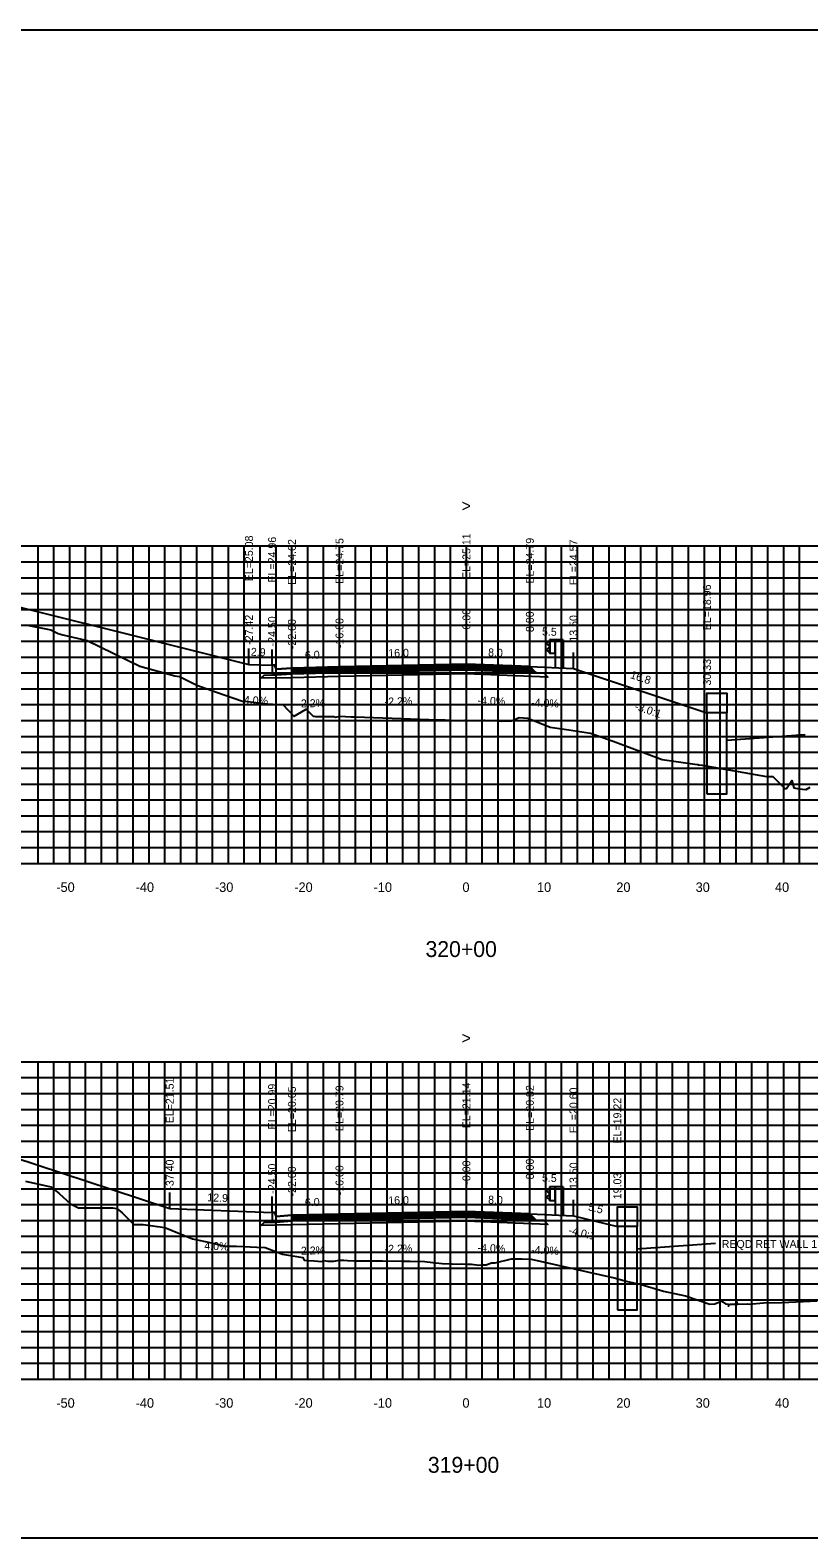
# Model space of a CAD drawing. Extents: x 1797652 to 1804145, y 245981 to 250269.
# Drawn here: x 1802916 to 1803014.2, y 250079.4 to 250269.4 of the extents above; entities that cross this region are included whole.
import ezdxf

# ---------------------------------------------------------------- set-up
doc = ezdxf.new("R2010")
doc.units = 0
for name, color, linetype in [('1', 7, 'Continuous'), ('10', 7, 'Continuous'), ('3', 7, 'Continuous'), ('4', 7, 'Continuous'), ('60', 7, 'Continuous'), ('BASE', 7, 'Continuous'), ('CL-CNST', 7, 'Continuous'), ('Level 1', 7, 'Continuous'), ('Level 62', 7, 'Continuous'), ('LOWER BINDER', 7, 'Continuous'), ('M-ROADS', 7, 'Continuous'), ('UPPER BINDER', 7, 'Continuous'), ('WEARING', 7, 'Continuous')]:
    doc.layers.add(name, color=color, linetype=linetype)

msp = doc.modelspace()

# ---------------------------------------------------------------- linework, layer by layer
for p, q in [((1802943.59, 250189.51), (1802943.59, 250191.51)), ((1802946.5, 250189.39), (1802946.5, 250191.39)), ((1802949, 250189.05), (1802949, 250191.05)), ((1802955, 250189.19), (1802955, 250191.19)), ((1802971, 250189.54), (1802971, 250191.54)), ((1802979, 250189.22), (1802979, 250191.22)), ((1802984.5, 250189), (1802984.5, 250191)), ((1803001.33, 250183.39), (1803001.33, 250185.39)), ((1802933.6, 250120.94), (1802933.6, 250122.94)), ((1802946.5, 250120.43), (1802946.5, 250122.43)), ((1802949, 250120.09), (1802949, 250122.09)), ((1802955, 250120.22), (1802955, 250122.22)), ((1802971, 250120.57), (1802971, 250122.57)), ((1802979, 250120.25), (1802979, 250122.25)), ((1802984.5, 250120.03), (1802984.5, 250122.03)), ((1802990.03, 250118.65), (1802990.03, 250120.65))]:
    msp.add_line(p, q)
for points in [[(1802821, 250079.43), (1803121, 250079.43), (1803121, 250269.43), (1802821, 250269.43)], [(1802949, 250189.05), (1802947, 250188.89), (1802946.83, 250189.39), (1802946.5, 250189.39), (1802946.5, 250188.17), (1802947, 250188.17), (1802949, 250188.33)], [(1802949, 250120.09), (1802947, 250119.93), (1802946.83, 250120.43), (1802946.5, 250120.43), (1802946.5, 250119.21), (1802947, 250119.21), (1802949, 250119.37)]]:
    msp.add_lwpolyline(points, close=True)
at = {"layer": '3'}
for p, q in [((1803013.72, 250180.62), (1803003.83, 250179.91)), ((1803002.42, 250116.53), (1802992.53, 250115.82))]:
    msp.add_line(p, q, dxfattribs=at)
at = {"layer": '60'}
for p, q in [((1802821, 250164.43), (1803121, 250164.43)), ((1802921, 250164.37), (1802921, 250164.43)), ((1802931, 250164.37), (1802931, 250164.43)), ((1802941, 250164.37), (1802941, 250164.43)), ((1802951, 250164.37), (1802951, 250164.43)), ((1802961, 250164.37), (1802961, 250164.43)), ((1802971, 250164.37), (1802971, 250164.43)), ((1802981, 250164.37), (1802981, 250164.43)), ((1802991, 250164.37), (1802991, 250164.43)), ((1803001, 250164.37), (1803001, 250164.43)), ((1803011, 250164.37), (1803011, 250164.43)), ((1802821, 250099.43), (1803121, 250099.43)), ((1802921, 250099.37), (1802921, 250099.43)), ((1802931, 250099.37), (1802931, 250099.43)), ((1802941, 250099.37), (1802941, 250099.43)), ((1802951, 250099.37), (1802951, 250099.43)), ((1802961, 250099.37), (1802961, 250099.43)), ((1802971, 250099.37), (1802971, 250099.43)), ((1802981, 250099.37), (1802981, 250099.43)), ((1802991, 250099.37), (1802991, 250099.43)), ((1803001, 250099.37), (1803001, 250099.43)), ((1803011, 250099.37), (1803011, 250099.43))]:
    msp.add_line(p, q, dxfattribs=at)
at = {"layer": 'BASE'}
for points in [[(1802949, 250188.33), (1802955, 250188.47), (1802971, 250188.82), (1802979.75, 250188.47), (1802980.75, 250188.43), (1802981.27, 250187.91), (1802971, 250188.32), (1802955, 250187.97), (1802949, 250187.83), (1802945.09, 250187.75), (1802945.5, 250188.15), (1802946.5, 250188.17), (1802947, 250188.17)], [(1802949, 250119.37), (1802955, 250119.5), (1802971, 250119.85), (1802979.75, 250119.5), (1802980.75, 250119.46), (1802981.27, 250118.94), (1802971, 250119.35), (1802955, 250119), (1802949, 250118.87), (1802945.09, 250118.78), (1802945.5, 250119.18), (1802946.5, 250119.21), (1802947, 250119.21)]]:
    msp.add_lwpolyline(points, close=True, dxfattribs=at)
at = {"layer": 'CL-CNST'}
for points in [[(1802908.08, 250198.35), (1802928.03, 250193.38), (1802943.59, 250189.51)], [(1802943.59, 250189.51), (1802946.5, 250189.39), (1802946.83, 250189.39), (1802947, 250188.89), (1802949, 250189.05), (1802955, 250189.19), (1802971, 250189.54), (1802979, 250189.22), (1802984.5, 250189), (1803001.33, 250183.39)], [(1802821, 250132.88), (1802827, 250133.14), (1802834.09, 250133.44), (1802839.28, 250133.66), (1802849.92, 250134.11), (1802851.54, 250134.17), (1802853.51, 250134.26), (1802863.8, 250134.69), (1802872.2, 250135.05), (1802876.07, 250135.21), (1802876.73, 250135.18), (1802877.09, 250135.17), (1802877.12, 250135.13), (1802877.14, 250135.11), (1802880.65, 250135.02), (1802886.29, 250134.87), (1802887.43, 250134.83), (1802888.33, 250134.79), (1802889.97, 250134.72), (1802891.91, 250134.64), (1802926.35, 250123.32), (1802933.6, 250120.94)], [(1802933.6, 250120.94), (1802946.5, 250120.43), (1802946.83, 250120.43), (1802947, 250119.93), (1802949, 250120.09), (1802955, 250120.22), (1802971, 250120.57), (1802979, 250120.25), (1802984.5, 250120.03), (1802990.03, 250118.65)]]:
    msp.add_lwpolyline(points, dxfattribs=at)
for points in [[(1803003.83, 250183.39), (1803001.33, 250183.39), (1803001.33, 250185.89), (1803003.83, 250185.89)], [(1803001.33, 250173.18), (1803003.83, 250173.18), (1803003.83, 250183.39), (1803001.33, 250183.39)], [(1802992.53, 250118.65), (1802990.03, 250118.65), (1802990.03, 250121.15), (1802992.53, 250121.15)], [(1802990.03, 250108.18), (1802992.53, 250108.18), (1802992.53, 250118.65), (1802990.03, 250118.65)]]:
    msp.add_lwpolyline(points, close=True, dxfattribs=at)
at = {"layer": 'Level 1'}
for p, q in [((1802981.46, 250192.47), (1802981.1, 250192.17)), ((1802981.1, 250192.1), (1802981.46, 250191.81)), ((1802981.46, 250192.62), (1802981.46, 250190.87)), ((1802983.21, 250192.62), (1802981.46, 250192.62)), ((1802981.51, 250192.62), (1802981.51, 250190.87)), ((1802982.16, 250192.62), (1802982.16, 250190.87)), ((1802982.21, 250192.62), (1802982.21, 250189.09)), ((1802983.21, 250192.62), (1802983.21, 250189.05)), ((1802981.46, 250191.67), (1802981.1, 250191.37)), ((1802981.1, 250191.3), (1802981.46, 250191.02)), ((1802982.21, 250190.87), (1802981.46, 250190.87)), ((1802981.46, 250123.65), (1802981.46, 250121.9)), ((1802983.21, 250123.65), (1802981.46, 250123.65)), ((1802981.51, 250123.65), (1802981.51, 250121.9)), ((1802982.16, 250123.65), (1802982.16, 250121.9)), ((1802982.21, 250123.65), (1802982.21, 250120.12)), ((1802983.21, 250123.65), (1802983.21, 250120.08)), ((1802981.46, 250123.5), (1802981.1, 250123.2)), ((1802981.1, 250123.13), (1802981.46, 250122.84)), ((1802981.46, 250122.7), (1802981.1, 250122.4)), ((1802981.1, 250122.33), (1802981.46, 250122.05)), ((1802982.21, 250121.9), (1802981.46, 250121.9))]:
    msp.add_line(p, q, dxfattribs=at)
for centre in [(1802981.13, 250192.13), (1802981.13, 250191.34), (1802981.13, 250123.16), (1802981.13, 250122.37)]:
    msp.add_arc(centre, 0.05, 135, 226.6208, dxfattribs=at)
at = {"layer": 'Level 62'}
for p, q in [((1802821, 250204.43), (1803121, 250204.43)), ((1802917, 250164.43), (1802917, 250204.43)), ((1802919, 250164.43), (1802919, 250204.43)), ((1802921, 250164.43), (1802921, 250204.43)), ((1802923, 250164.43), (1802923, 250204.43)), ((1802925, 250164.43), (1802925, 250204.43)), ((1802927, 250164.43), (1802927, 250204.43)), ((1802929, 250164.43), (1802929, 250204.43)), ((1802931, 250164.43), (1802931, 250204.43)), ((1802933, 250164.43), (1802933, 250204.43)), ((1802935, 250164.43), (1802935, 250204.43)), ((1802937, 250164.43), (1802937, 250204.43)), ((1802939, 250164.43), (1802939, 250204.43)), ((1802941, 250164.43), (1802941, 250204.43)), ((1802943, 250164.43), (1802943, 250204.43)), ((1802945, 250164.43), (1802945, 250204.43)), ((1802947, 250164.43), (1802947, 250204.43)), ((1802949, 250164.43), (1802949, 250204.43)), ((1802951, 250164.43), (1802951, 250204.43)), ((1802953, 250164.43), (1802953, 250204.43)), ((1802955, 250164.43), (1802955, 250204.43)), ((1802957, 250164.43), (1802957, 250204.43)), ((1802959, 250164.43), (1802959, 250204.43)), ((1802961, 250164.43), (1802961, 250204.43)), ((1802963, 250164.43), (1802963, 250204.43)), ((1802965, 250164.43), (1802965, 250204.43)), ((1802967, 250164.43), (1802967, 250204.43)), ((1802969, 250164.43), (1802969, 250204.43)), ((1802971, 250164.43), (1802971, 250204.43)), ((1802973, 250164.43), (1802973, 250204.43)), ((1802975, 250164.43), (1802975, 250204.43)), ((1802977, 250164.43), (1802977, 250204.43)), ((1802979, 250164.43), (1802979, 250204.43)), ((1802981, 250164.43), (1802981, 250204.43)), ((1802983, 250164.43), (1802983, 250204.43)), ((1802985, 250164.43), (1802985, 250204.43)), ((1802987, 250164.43), (1802987, 250204.43)), ((1802989, 250164.43), (1802989, 250204.43)), ((1802991, 250164.43), (1802991, 250204.43)), ((1802993, 250164.43), (1802993, 250204.43)), ((1802995, 250164.43), (1802995, 250204.43)), ((1802997, 250164.43), (1802997, 250204.43)), ((1802999, 250164.43), (1802999, 250204.43)), ((1803001, 250164.43), (1803001, 250204.43)), ((1803003, 250164.43), (1803003, 250204.43)), ((1803005, 250164.43), (1803005, 250204.43)), ((1803007, 250164.43), (1803007, 250204.43)), ((1803009, 250164.43), (1803009, 250204.43)), ((1803011, 250164.43), (1803011, 250204.43)), ((1803013, 250164.43), (1803013, 250204.43)), ((1802821, 250202.43), (1803121, 250202.43)), ((1802821, 250200.43), (1803121, 250200.43)), ((1802821, 250198.43), (1803121, 250198.43)), ((1802821, 250196.43), (1803121, 250196.43)), ((1802821, 250194.43), (1803121, 250194.43)), ((1802821, 250192.43), (1803121, 250192.43)), ((1802821, 250190.43), (1803121, 250190.43)), ((1802821, 250188.43), (1803121, 250188.43)), ((1802821, 250186.43), (1803121, 250186.43)), ((1802821, 250184.43), (1803121, 250184.43)), ((1802821, 250182.43), (1803121, 250182.43)), ((1802821, 250180.43), (1803121, 250180.43)), ((1802821, 250178.43), (1803121, 250178.43)), ((1802821, 250176.43), (1803121, 250176.43)), ((1802821, 250174.43), (1803121, 250174.43)), ((1802821, 250172.43), (1803121, 250172.43)), ((1802821, 250170.43), (1803121, 250170.43)), ((1802821, 250168.43), (1803121, 250168.43)), ((1802821, 250166.43), (1803121, 250166.43)), ((1802821, 250164.43), (1803121, 250164.43)), ((1802821, 250139.43), (1803121, 250139.43)), ((1802917, 250099.43), (1802917, 250139.43)), ((1802919, 250099.43), (1802919, 250139.43)), ((1802921, 250099.43), (1802921, 250139.43)), ((1802923, 250099.43), (1802923, 250139.43)), ((1802925, 250099.43), (1802925, 250139.43)), ((1802927, 250099.43), (1802927, 250139.43)), ((1802929, 250099.43), (1802929, 250139.43)), ((1802931, 250099.43), (1802931, 250139.43)), ((1802933, 250099.43), (1802933, 250139.43)), ((1802935, 250099.43), (1802935, 250139.43)), ((1802937, 250099.43), (1802937, 250139.43)), ((1802939, 250099.43), (1802939, 250139.43)), ((1802941, 250099.43), (1802941, 250139.43)), ((1802943, 250099.43), (1802943, 250139.43)), ((1802945, 250099.43), (1802945, 250139.43)), ((1802947, 250099.43), (1802947, 250139.43)), ((1802949, 250099.43), (1802949, 250139.43)), ((1802951, 250099.43), (1802951, 250139.43)), ((1802953, 250099.43), (1802953, 250139.43)), ((1802955, 250099.43), (1802955, 250139.43)), ((1802957, 250099.43), (1802957, 250139.43)), ((1802959, 250099.43), (1802959, 250139.43)), ((1802961, 250099.43), (1802961, 250139.43)), ((1802963, 250099.43), (1802963, 250139.43)), ((1802965, 250099.43), (1802965, 250139.43)), ((1802967, 250099.43), (1802967, 250139.43)), ((1802969, 250099.43), (1802969, 250139.43)), ((1802971, 250099.43), (1802971, 250139.43)), ((1802973, 250099.43), (1802973, 250139.43)), ((1802975, 250099.43), (1802975, 250139.43)), ((1802977, 250099.43), (1802977, 250139.43)), ((1802979, 250099.43), (1802979, 250139.43)), ((1802981, 250099.43), (1802981, 250139.43)), ((1802983, 250099.43), (1802983, 250139.43)), ((1802985, 250099.43), (1802985, 250139.43)), ((1802987, 250099.43), (1802987, 250139.43)), ((1802989, 250099.43), (1802989, 250139.43)), ((1802991, 250099.43), (1802991, 250139.43)), ((1802993, 250099.43), (1802993, 250139.43)), ((1802995, 250099.43), (1802995, 250139.43)), ((1802997, 250099.43), (1802997, 250139.43)), ((1802999, 250099.43), (1802999, 250139.43)), ((1803001, 250099.43), (1803001, 250139.43)), ((1803003, 250099.43), (1803003, 250139.43)), ((1803005, 250099.43), (1803005, 250139.43)), ((1803007, 250099.43), (1803007, 250139.43)), ((1803009, 250099.43), (1803009, 250139.43)), ((1803011, 250099.43), (1803011, 250139.43)), ((1803013, 250099.43), (1803013, 250139.43)), ((1802821, 250137.43), (1803121, 250137.43)), ((1802821, 250135.43), (1803121, 250135.43)), ((1802821, 250133.43), (1803121, 250133.43)), ((1802821, 250131.43), (1803121, 250131.43)), ((1802821, 250129.43), (1803121, 250129.43)), ((1802821, 250127.43), (1803121, 250127.43)), ((1802821, 250125.43), (1803121, 250125.43)), ((1802821, 250123.43), (1803121, 250123.43)), ((1802821, 250121.43), (1803121, 250121.43)), ((1802821, 250119.43), (1803121, 250119.43)), ((1802821, 250117.43), (1803121, 250117.43)), ((1802821, 250115.43), (1803121, 250115.43)), ((1802821, 250113.43), (1803121, 250113.43)), ((1802821, 250111.43), (1803121, 250111.43)), ((1802821, 250109.43), (1803121, 250109.43)), ((1802821, 250107.43), (1803121, 250107.43)), ((1802821, 250105.43), (1803121, 250105.43)), ((1802821, 250103.43), (1803121, 250103.43)), ((1802821, 250101.43), (1803121, 250101.43)), ((1802821, 250099.43), (1803121, 250099.43))]:
    msp.add_line(p, q, dxfattribs=at)
at = {"layer": 'LOWER BINDER'}
for points in [[(1802955, 250188.85), (1802971, 250189.2), (1802979.36, 250188.86), (1802979.55, 250188.67), (1802971, 250189.01), (1802955, 250188.66), (1802949, 250188.52), (1802949, 250188.71)], [(1802955, 250188.66), (1802971, 250189.01), (1802979.55, 250188.67), (1802979.75, 250188.47), (1802971, 250188.82), (1802955, 250188.47), (1802949, 250188.33), (1802949, 250188.52)], [(1802955, 250119.88), (1802971, 250120.23), (1802979.36, 250119.9), (1802979.55, 250119.7), (1802971, 250120.04), (1802955, 250119.69), (1802949, 250119.56), (1802949, 250119.75)], [(1802955, 250119.69), (1802971, 250120.04), (1802979.55, 250119.7), (1802979.75, 250119.5), (1802971, 250119.85), (1802955, 250119.5), (1802949, 250119.37), (1802949, 250119.56)]]:
    msp.add_lwpolyline(points, close=True, dxfattribs=at)
at = {"layer": 'M-ROADS'}
for points in [[(1802915.41, 250194.48), (1802918.6, 250193.86), (1802919.55, 250193.38), (1802920.14, 250193.23), (1802923.17, 250192.5), (1802929.85, 250189.29), (1802934.26, 250188.06), (1802934.85, 250187.97), (1802937.01, 250186.87), (1802939.49, 250186.01), (1802942.77, 250184.88), (1802942.93, 250184.88), (1802943.11, 250184.88), (1802945.78, 250184.53), (1802947.39, 250184.43), (1802947.86, 250184.43), (1802949.26, 250182.99), (1802949.27, 250182.97), (1802949.28, 250182.98), (1802950.8, 250183.85), (1802951.7, 250182.97), (1802951.78, 250182.96), (1802951.97, 250182.95), (1802953.23, 250182.92), (1802953.97, 250182.94), (1802954.3, 250182.92), (1802954.48, 250182.87), (1802955.04, 250182.96), (1802955.74, 250182.93), (1802956.46, 250182.9), (1802956.99, 250182.88), (1802967.42, 250182.53), (1802968.31, 250182.5), (1802969.49, 250182.43), (1802969.56, 250182.43), (1802969.73, 250182.43), (1802970.8, 250182.49), (1802970.85, 250182.49), (1802972.05, 250182.42), (1802972.41, 250182.44), (1802973.21, 250182.49), (1802973.31, 250182.49), (1802974.51, 250182.42), (1802974.56, 250182.42), (1802975.38, 250182.37), (1802976.69, 250182.4), (1802977.64, 250182.82), (1802978.75, 250182.73), (1802981.57, 250181.6), (1802983.92, 250181.25), (1802986.63, 250180.85), (1802989.49, 250179.85), (1802995.69, 250177.5), (1803000.11, 250176.89), (1803000.14, 250176.88), (1803000.2, 250176.87), (1803000.32, 250176.84), (1803000.71, 250176.79), (1803008.84, 250175.36), (1803009.63, 250175.36), (1803011.15, 250173.86), (1803011.36, 250173.86), (1803012.01, 250174.86), (1803012.27, 250173.93), (1803012.96, 250173.81), (1803013.8, 250173.72), (1803013.82, 250173.74), (1803014.33, 250174.04)], [(1802915.42, 250124.4), (1802918.62, 250123.68), (1802919.66, 250122.82), (1802921.08, 250121.54), (1802922.09, 250121.02), (1802924.19, 250121.02), (1802926.42, 250121.02), (1802926.93, 250120.93), (1802927.59, 250120.38), (1802929.07, 250118.92), (1802929.64, 250118.92), (1802930.25, 250118.92), (1802932.99, 250118.54), (1802936.49, 250117.1), (1802938.86, 250116.62), (1802940.53, 250116.2), (1802941.26, 250116.2), (1802942.03, 250116.2), (1802944.56, 250116.08), (1802945.62, 250116.03), (1802947.8, 250115.18), (1802950.37, 250114.77), (1802950.56, 250114.43), (1802951.09, 250114.4), (1802951.81, 250114.36), (1802952.75, 250114.25), (1802952.9, 250114.28), (1802953.02, 250114.38), (1802953.53, 250114.32), (1802953.98, 250114.3), (1802954.27, 250114.31), (1802954.99, 250114.43), (1802955.56, 250114.42), (1802955.99, 250114.4), (1802956.81, 250114.36), (1802957.82, 250114.33), (1802960.44, 250114.33), (1802963.12, 250114.31), (1802963.89, 250114.31), (1802965.76, 250114.25), (1802966.04, 250114.22), (1802967.14, 250114.1), (1802967.94, 250114.01), (1802968.94, 250113.97), (1802969.2, 250113.96), (1802969.93, 250113.93), (1802970.39, 250113.96), (1802971.12, 250113.93), (1802971.64, 250113.91), (1802972.56, 250113.81), (1802972.98, 250113.85), (1802973.47, 250113.82), (1802974.18, 250114.08), (1802974.64, 250114.07), (1802976.67, 250114.59), (1802978.05, 250114.59), (1802979.16, 250114.55), (1802989.61, 250112.18), (1802991.16, 250111.79), (1802993.04, 250111.34), (1802995.86, 250110.52), (1802998.61, 250109.95), (1803001.68, 250108.9), (1803002.33, 250108.94), (1803003.23, 250109.3), (1803003.36, 250109.14), (1803003.66, 250108.92), (1803003.66, 250108.92), (1803004.02, 250108.89), (1803004.03, 250108.64), (1803004.09, 250108.81), (1803004.27, 250108.89), (1803004.42, 250108.89), (1803004.67, 250108.88), (1803004.81, 250108.88), (1803004.87, 250108.87), (1803005.11, 250109.16), (1803005.13, 250108.9), (1803005.23, 250108.9), (1803006.42, 250108.91), (1803006.65, 250108.9), (1803008.46, 250109.04), (1803010.75, 250109.09), (1803015.23, 250109.28)]]:
    msp.add_lwpolyline(points, dxfattribs=at)
at = {"layer": 'UPPER BINDER'}
for points in [[(1802979.36, 250188.86), (1802979.16, 250189.06), (1802971, 250189.39), (1802955, 250189.04), (1802949, 250188.9), (1802949, 250188.71), (1802955, 250188.85), (1802971, 250189.2)], [(1802979.36, 250119.9), (1802979.16, 250120.09), (1802971, 250120.42), (1802955, 250120.07), (1802949, 250119.94), (1802949, 250119.75), (1802955, 250119.88), (1802971, 250120.23)]]:
    msp.add_lwpolyline(points, close=True, dxfattribs=at)
at = {"layer": 'WEARING'}
for points in [[(1802979.16, 250189.06), (1802979, 250189.22), (1802971, 250189.54), (1802955, 250189.19), (1802949, 250189.05), (1802949, 250188.9), (1802955, 250189.04), (1802971, 250189.39)], [(1802979.16, 250120.09), (1802979, 250120.25), (1802971, 250120.57), (1802955, 250120.22), (1802949, 250120.09), (1802949, 250119.94), (1802955, 250120.07), (1802971, 250120.42)]]:
    msp.add_lwpolyline(points, close=True, dxfattribs=at)

# ---------------------------------------------------------------- texts
for s, rotation, p in [('-3.0:1', 341.5652, (1802992.13, 250183.82)), ('-4.0:1', 345.9638, (1802983.81, 250117.77))]:
    msp.add_text(s, height=1, rotation=rotation).set_placement(p)
at = {"layer": '1'}
for s, p in [('320+00', (1802965.84, 250152.63)), ('319+00', (1802966.14, 250087.63))]:
    msp.add_text(s, height=2, dxfattribs=at).set_placement(p)
at = {"layer": '10'}
for s, p in [('-50', (1802919.3, 250160.83)), ('-40', (1802929.3, 250160.83)), ('-30', (1802939.3, 250160.83)), ('-20', (1802949.3, 250160.83)), ('-10', (1802959.3, 250160.83)), ('0', (1802970.5, 250160.83)), ('10', (1802979.9, 250160.83)), ('20', (1802989.9, 250160.83)), ('30', (1802999.9, 250160.83)), ('40', (1803009.9, 250160.83)), ('-50', (1802919.3, 250095.83)), ('-40', (1802929.3, 250095.83)), ('-30', (1802939.3, 250095.83)), ('-20', (1802949.3, 250095.83)), ('-10', (1802959.3, 250095.83)), ('0', (1802970.5, 250095.83)), ('10', (1802979.9, 250095.83)), ('20', (1802989.9, 250095.83)), ('30', (1802999.9, 250095.83)), ('40', (1803009.9, 250095.83))]:
    msp.add_text(s, height=1.2, dxfattribs=at).set_placement(p)
at = {"layer": '3'}
for s, p in [('EL=25.08', (1802944.09, 250199.98)), ('EL=24.96', (1802947, 250199.82)), ('EL=24.75', (1802955.5, 250199.66)), ('EL=25.11', (1802971.5, 250200.26)), ('EL=24.79', (1802979.5, 250199.69)), ('EL=24.62', (1802949.5, 250199.53)), ('EL=24.57', (1802985, 250199.47)), ('EL=18.96', (1803001.83, 250193.81)), ('0.00', (1802971.5, 250193.9)), ('8.00', (1802979.5, 250193.58)), ('-27.42', (1802944.09, 250191.97)), ('-24.50', (1802947, 250191.77)), ('-22.00', (1802949.5, 250191.43)), ('-16.00', (1802955.5, 250191.56)), ('13.50', (1802985, 250192.37)), ('30.33', (1803001.83, 250186.84)), ('EL=21.51', (1802934.1, 250131.67)), ('EL=20.99', (1802947, 250130.9)), ('EL=20.65', (1802949.5, 250130.56)), ('EL=20.79', (1802955.5, 250130.69)), ('EL=21.14', (1802971.5, 250131.04)), ('EL=20.82', (1802979.5, 250130.72)), ('EL=20.60', (1802985, 250130.42)), ('EL=19.22', (1802990.53, 250129.12)), ('-37.40', (1802934.1, 250123.32)), ('-24.50', (1802947, 250122.8)), ('-22.00', (1802949.5, 250122.46)), ('-16.00', (1802955.5, 250122.6)), ('-0.00', (1802971.5, 250123.94)), ('8.00', (1802979.5, 250124.61)), ('13.50', (1802985, 250123.4)), ('19.03', (1802990.53, 250122.1))]:
    msp.add_text(s, height=1, rotation=90, dxfattribs=at).set_placement(p)
msp.add_text('REQD RET WALL 1', height=1, dxfattribs=at).set_placement((1803003.19, 250115.97))
at = {"layer": '4'}
for s, rotation, p in [('5.5', 357.7094, (1802980.51, 250193.17)), ('2.9', 357.7094, (1802943.81, 250190.6)), ('6.0', 1.2603, (1802950.65, 250190.19)), ('16.0', 1.2603, (1802961.16, 250190.42)), ('8.0', 357.7094, (1802973.72, 250190.53)), ('16.8', 341.5652, (1802991.58, 250187.8)), ('4.0%', 357.7094, (1802942.93, 250184.53)), ('-2.2%', 1.2603, (1802949.7, 250184.07)), ('-2.2%', 1.2603, (1802960.7, 250184.31)), ('-4.0%', 357.7094, (1802972.39, 250184.48)), ('-4.0%', 357.7094, (1802979.14, 250184.21)), ('5.5', 357.7094, (1802980.51, 250124.34)), ('12.9', 357.7094, (1802938.32, 250121.85)), ('6.0', 1.2603, (1802950.65, 250121.22)), ('16.0', 1.2603, (1802961.16, 250121.45)), ('8.0', 357.7094, (1802973.72, 250121.56)), ('5.5', 345.9638, (1802986.29, 250120.72)), ('4.0%', 357.7094, (1802937.94, 250115.76)), ('-2.2%', 1.2603, (1802949.7, 250115.1)), ('-2.2%', 1.2603, (1802960.7, 250115.34)), ('-4.0%', 357.7094, (1802972.39, 250115.51)), ('-4.0%', 357.7094, (1802979.14, 250115.24))]:
    msp.add_text(s, height=1, rotation=rotation, dxfattribs=at).set_placement(p)
at = {"layer": '60'}
for p in [(1802970.39, 250208.75), (1802970.39, 250141.68)]:
    msp.add_text('>', height=1.5, dxfattribs=at).set_placement(p)

doc.saveas('drawing.dxf')
